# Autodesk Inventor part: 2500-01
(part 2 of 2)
sketch "Sketch56"
  geometry: L1 (2, -4.8)-(12, -4.8) reference; L2 (10.75, -6.3)-(3.25, -6.3); L3 (3.25, -6.3)-(3.25, -24.3); L4 (3.25, -24.3)-(10.75, -24.3); L5 (10.75, -24.3)-(10.75, -6.3); L6 (2, -24.3)-(12, -24.3) reference; 2 further points
  constraints: 8 end point, 2 midpoint, 2 parallel, 1 collinear, 1 horizontal, 1 perpendicular, 1 vertical alignment
  dimensions: "d457" = 18 distance of L4.end L2.start; "d458" = 7.5 distance of L2.start L2.end
extrude "Extrusion54" cut sketch "Sketch56" distance "d459" = 10; taper "d460" = 0 deg
sketch "Sketch57"
  geometry: L1 (10.75, -8.8)-(10.75, -6.3) reference; L2 (3.25, -6.3)-(3.25, -24.3) reference; L3 (10.65, -7.3)-(5.65, -7.3); L4 (5.65, -7.3)-(5.65, -23.3); L5 (5.65, -23.3)-(10.65, -23.3); L6 (10.65, -23.3)-(10.65, -7.3); 2 further points
  constraints: 8 end point, 2 midpoint, 2 parallel, 1 horizontal, 1 horizontal alignment, 1 perpendicular
  dimensions: "d461" = 0.1 distance between parallel lines of L1 L6; "d462" = 16 distance of L5.end L3.start; "d463" = 5 distance of L3.start L3.end
extrude "Extrusion55" join sketch "Sketch57" distance "d464" = 15; taper "d465" = 0 deg
chamfer "Chamfer15" distance "d466" = 3; stored, may be unused: second distance "d467" = 2, angle "d468" = 70 deg
sketch "Sketch58"
  geometry: L1 (5.65, -23.3)-(5.65, -7.3) reference; L2 (3.25, -6.3)-(3.25, -24.3) reference; L3 (5.55, -10.3)-(3.25, -10.3); L4 (3.25, -10.3)-(3.25, -20.3); L5 (3.25, -20.3)-(5.55, -20.3); L6 (5.55, -20.3)-(5.55, -10.3); L7 (5.65, -10.3)-(10.65, -10.3) reference; L8 (10.65, -20.3)-(5.65, -20.3) reference
  constraints: 8 end point, 2 collinear, 2 parallel, 1 horizontal, 1 perpendicular, 1 point on line
  dimensions: "d469" = 0.1 distance between parallel lines of L1 L6
extrude "Extrusion56" join sketch "Sketch58" distance "d470" = 9; taper "d471" = 0 deg
sketch "Sketch59"
  geometry: L1 (10.65, -10.3)-(10.65, -20.3) reference; L2 (5.65, -20.3)-(5.65, -10.3) reference; L3 (9.75, -11.8)-(6.25, -11.8); L4 (6.25, -11.8)-(6.25, -14.55); L5 (6.25, -14.55)-(9.75, -14.55); L6 (9.75, -14.55)-(9.75, -11.8); L7 (9.75, -16.05)-(6.25, -16.05); L8 (6.25, -16.05)-(6.25, -18.8); L9 (6.25, -18.8)-(9.75, -18.8); L10 (9.75, -18.8)-(9.75, -16.05); L11 (13.569, -15.3)-(3.512, -15.3); 1 further point
  constraints: 18 end point, 4 parallel, 3 perpendicular, 2 collinear, 2 horizontal, 1 midpoint, 1 point on line, 2 other
  dimensions: "d472" = 1.5 distance between parallel lines of L7 L5; "d473" = 7 distance between parallel lines of L9 L3; "d474" = 3.5 distance of L8.end L9.end; "d475" = 0.6 distance between parallel lines of L2 L8
extrude "Extrusion57" cut sketch "Sketch59" distance "d476" = 5; taper "d477" = 0 deg
workplane "Work Plane9"
sketch "Sketch60"
  geometry: L1 (-8.275, -0.875)-(-18.71, -0.875); L2 (-15, -2.25)-(-15, 0.5) reference; L3 (-9.715, -0.875)-(-9.715, -2.302); L4 (-9.715, -2.302)-(-14.223, -2.302); L5 (-9.715, -0.875)-(-15.623, -0.875); A1 r 1.864 centre (-13.799, -0.487) between (-15.623, -0.875) and (-14.223, -2.302); 1 further point
  constraints: 8 end point, 3 point on line, 2 point on circle, 1 centre point, 1 collinear, 1 horizontal, 1 midpoint, 1 parallel, 1 perpendicular
revolve "Revolution9" sketch "Sketch60" stored, may be unused: angle "d479" = 90 deg
sketch "Sketch61"
  geometry: L1 (37, -4.5)-(29.3, -4.5) reference; L2 (27.76, 0)-(38.54, 0) reference; L3 (30.9, 0)-(35.4, 0); L4 (35.4, 0)-(35.4, -5.813); L5 (35.4, -5.813)-(30.9, -5.813); L6 (30.9, -5.813)-(30.9, 0); L7 (35.4, 0)-(35.4, 5.813); L8 (35.4, 5.813)-(30.9, 5.813); L9 (30.9, 5.813)-(30.9, 0); 4 further points
  constraints: 14 end point, 4 symmetric about line, 2 midpoint, 2 parallel, 1 horizontal, 1 perpendicular, 1 point on line, 1 vertical alignment
  dimensions: "d481" = 4.5 distance between parallel lines of L4 L6
revolve "Revolution10" stored, may be unused: angle "d482" = 90 deg
extrude "Extrusion58" cut sketch "Sketch61" stored distance "d483" = 5; taper "d484" = 0 deg
sketch "Sketch62"
  geometry: L1 (0, 0)-(-7.7, 0) reference; L2 (-1.6, 0)-(-6.1, 0); L3 (-6.1, 0)-(-6.1, 3.2); L4 (-6.1, 3.2)-(-1.6, 3.2); L5 (-1.6, 3.2)-(-1.6, 0); L6 (0, 0)-(-7.7, 0) reference; 3 further points
  constraints: 8 end point, 3 midpoint, 2 coincident, 2 parallel, 1 horizontal, 1 perpendicular, 1 point on line
  dimensions: "d485" = 4.5 distance between parallel lines of L3 L5; "d486" = 3.2 distance of L4.end L2.start
extrude "Extrusion59" cut sketch "Sketch62" stored distance "d487" = 5; taper "d488" = 0 deg
sketch "Sketch63"
  geometry: C1 r 4.75 at (4.5, 5.3); C2 r 5.05 at (4.5, 5.3); A1 r 5.813 centre (4.5, 5.3) between (10.313, 5.3) and (-1.243, 6.2) reference
  constraints: 2 centre point, 2 coincident
  dimensions: "d489" = 9.5 diameter of C1; "d490" = 0.3 radial gap between concentric circles of C1 C2
extrude "Extrusion60" join sketch "Sketch63" distance "d491" = 4.3; taper "d492" = 0 deg
sketch "Sketch64"
  geometry: C1 r 4.65 at (5.813, 5.3); C2 r 3.85 at (5.813, 5.3); A1 r 5.813 centre (5.813, 5.3) between (11.626, 5.3) and (0.07, 6.2) reference; A2 r 4.75 centre (5.813, 5.3) between (10.313, 3.779) and (1.313, 3.779) reference
  constraints: 2 centre point, 2 coincident
  dimensions: "d493" = 0.1 radial gap between concentric circles of C1 A2; "d494" = 0.8 radial gap between concentric circles of C2 C1
extrude "Extrusion61" join sketch "Sketch64" stored distance "d495" = 5; taper "d496" = 0 deg
mirror "Mirror4"
sketch "Sketch65"
  geometry: L1 (84.869, 5.621)-(89.6, 10.646); L2 (89.6, 10.646)-(89.6, 16); L3 (89.6, 16)-(91.6, 16); L4 (91.6, 16)-(91.6, 10); L5 (91.6, 10)-(86.251, 4.319); L6 (76.6, -8.4)-(78.6, -8.4); L7 (78.6, -8.5)-(76.5, -8.5) reference; L8 (76.5, -8.5)-(76.5, 4.5) reference; L9 (70, -10.5)-(78.6, -10.5) reference; L10 (78.6, -8.5)-(78.6, -10.5) reference; L11 (76.6, -8.4)-(76.6, -4.412); L12 (76.6, -4.412)-(78.14, -4.412); A1 r 36.899 centre (111.735, -19.673) between (84.869, 5.621) and (76.6, -8.4); A2 r 35 centre (111.735, -19.673) between (86.251, 4.319) and (78.6, -8.4)
  constraints: 16 end point, 5 point on circle, 4 perpendicular, 2 centre point, 2 parallel, 2 tangent, 1 concentric, 1 vertical, 1 vertical alignment
  dimensions: "d500" = 0.1 distance between parallel lines of L7 L6; "d501" = 0.1 distance from line of L8 L6.start; "d503" = 26.5 distance between parallel lines of L3 L9; "d504" = 13 distance between parallel lines of L10 L4; "d505" = 2 distance between parallel lines of L4 L2; "d507" = 6 distance of L3.end L4.end; "d508" = 35 radius of A2
extrude "Extrusion62" join sketch "Sketch65" stored distance "d509" = 5; taper "d510" = 0 deg
chamfer "Chamfer16" distance "d511" = 1.5; stored, may be unused: second distance "d512" = 2, angle "d513" = 60 deg
sketch "Sketch66"
  geometry: L1 (-24.4, 14.5)-(-24.4, 15) reference; L2 (-0.2, -5.5)-(-9.7, -5.5); L3 (-9.7, -5.5)-(-9.7, -10); L4 (-9.7, -10)-(-0.2, -10); L5 (-0.2, -10)-(-0.2, -5.5); L6 (0.6, -5.4)-(-5.4, -5.4) reference; L7 (-1.2, -27.8)-(-1.2, -7.6) reference
  constraints: 8 end point, 2 parallel, 2 perpendicular
  dimensions: "d514" = 0.1 distance between parallel lines of L6 L2; "d515" = 9.5 distance of L2.start L2.end; "d516" = 1 distance between parallel lines of L5 L7; "d517" = 4.5 distance of L2.end L3.end
extrude "Extrusion63" join sketch "Sketch66" distance "d518" = 3.5; taper "d519" = 0 deg
chamfer "Chamfer17" distance "d520" = 3; stored, may be unused: second distance "d521" = 2, angle "d522" = 30 deg
workplane "Work Plane10"
sketch "Sketch67"
  geometry: L1 (9, 54.1)-(4.7, 54.1) reference; L2 (1.5, 64)-(1.5, 33) reference; L3 (13.2, 36.3)-(13.2, 54.1) reference; L4 (3.5, 54.1)-(3.5, 71.236); L5 (3.5, 54.1)-(10.5, 54.1); L6 (10.5, 54.1)-(10.5, 61.6); L7 (11.5, 62.6)-(12, 62.6); L8 (12, 62.6)-(12, 66.019); L9 (4.7, 54.1)-(7.7, 54.1) reference; A1 r 41.613 centre (29.36, 103.839) between (3.5, 71.236) and (12, 66.019); A2 r 1 centre (11.5, 61.6) between (11.5, 62.6) and (10.5, 61.6); 1 further point
  constraints: 10 end point, 4 point on circle, 3 point on line, 2 centre point, 2 parallel, 2 perpendicular, 2 tangent, 1 collinear
  dimensions: "d524" = 7 distance of L4.start L5.end; "d525" = 2 distance between parallel lines of L2 L4; "d526" = 1.5 distance between parallel lines of L6 L8; "d527" = 8.5 distance of L5.end point (10.5, 62.6); "d528" = 1 radius of A2
extrude "Extrusion64" join sketch "Sketch67" stored distance "d529" = 3.5; taper "d530" = 0 deg
chamfer "Chamfer18" distance "d531" = 1; stored, may be unused: second distance "d532" = 2, angle "d533" = 60 deg
sketch "Sketch68"
  geometry: L1 (-18.4, 15)-(-12.719, 9.651) reference; L2 (-14.4, 3.3)-(-14.4, 11.234); L3 (-10.9, -10)-(-10.9, 5.869) reference; L4 (-10.9, 7.136)-(-10.9, 5.869) reference; L5 (-10.9, 1.279)-(-10.9, 8.054); L6 (-14.4, 3.3)-(-10.9, 1.279); L7 (-10.9, -0.1)-(-12.9, -0.1) reference; A1 r 35 centre (11.273, 35.135) between (-12.719, 9.651) and (0, 2) reference
  constraints: 6 end point, 2 collinear, 2 point on line, 1 point on circle
  dimensions: "d535" = 3.5 distance between parallel lines of L3 L2; "d536" = 60 deg angle of L5 L6; "d537" = 3.4 distance from line of L7 L2.start
extrude "Extrusion65" join sketch "Sketch68" distance "d538" = 1.5; taper "d539" = 0 deg
fillet "Fillet1" dims "d541" = 1
sketch "Sketch69"
  geometry: L1 (0, 0)-(66, 0) reference; L2 (66, 0)-(66, 5.603) reference; L3 (33, 47.913)-(33, -69.621) reference; L4 (66, 10)-(63.25, 10); L5 (63.25, 10)-(58.75, 0); L6 (66, 0)-(58.75, 0); L7 (66, 0)-(66, 10); L8 (48.5, -1.774)-(48.5, 31.075); L9 (48.5, 3.5)-(52.1, 3.5); L10 (52.1, 3.5)-(52.6, 6.5); L11 (52.6, 6.5)-(48.5, 6.5); L12 (48.5, 3.5)-(44.9, 3.5); L13 (44.9, 3.5)-(44.4, 6.5); L14 (44.4, 6.5)-(48.5, 6.5); L15 (2.75, 10)-(7.25, 0); L16 (0, 0)-(7.25, 0); L17 (0, 0)-(0, 5.603); L18 (0, 0)-(0, 10); L19 (0, 10)-(2.75, 10); L20 (13.9, 3.5)-(13.4, 6.5); L21 (17.5, 3.5)-(13.9, 3.5); L22 (13.4, 6.5)-(17.5, 6.5); L23 (17.5, 3.5)-(21.1, 3.5); L24 (21.1, 3.5)-(21.6, 6.5); L25 (21.6, 6.5)-(17.5, 6.5); L26 (17.5, -1.774)-(17.5, 31.075)
  constraints: 46 end point, 13 symmetric about line, 5 point on line, 2 perpendicular, 1 collinear, 1 parallel, 1 vertical
  dimensions: "d543" = 51.5 diameter of L5.end L3; "d544" = 60.5 diameter of L4.end L3; "d545" = 10 distance from line of L4 L5.end; "d547" = 31 diameter of L8.end L3; "d552" = 7.2 diameter of L9.end L8; "d553" = 8.2 diameter of L10.end L8; "d554" = 3 distance between parallel lines of L11 L9; "d555" = 3.5 distance between parallel lines of L1 L9
extrude "Extrusion66" cut sketch "Sketch69" distance "d556" = 15; taper "d557" = 0 deg
workplane "Work Plane11"
sketch "Sketch70"
  geometry: L1 (88.892, 9.5)-(85.521, 9.5); L2 (85.521, 9.5)-(85.521, 7.5); L3 (91.129, 9.5)-(88.521, 9.5) reference; A1 r 35 centre (113.306, -13.784) between (85.521, 7.5) and (81.788, 1.436); A2 r 36.899 centre (111.735, -19.673) between (84.869, 5.621) and (78.14, -4.412) reference; 2 further points
  constraints: 4 end point, 4 point on circle, 1 centre point, 1 coincident, 1 collinear, 1 horizontal, 1 perpendicular
  dimensions: "d558" = 3 distance from line of L2 L3.end; "d559" = 35 radius of A1; "d560" = 6 horizontal distance of L3.end point (82.521, 2.868); "d561" = 2 distance from line of L2.end L1
feature "Rib1" sketch "Sketch70" dims "d562" = 1, "d563" = 1, "d564" = 0
sketch "Sketch71"
  geometry: A1 r 21.005 centre (72.171, 19.068) between (87.057, 4.249) and (90.806, 9.376); A2 r 40.752 centre (115.94, -24.5) between (87.057, 4.249) and (78.536, -8.323)
  constraints: 4 point on circle, 2 centre point, 1 tangent
feature "Rib2" sketch "Sketch71" dims "d565" = 1, "d566" = 1, "d567" = 0
mirror "Mirror5"
workplane "Work Plane12"
sketch "Sketch72"
  geometry: L1 (-4.258, 9.661)-(-5, 10.7); L2 (-5, 10.7)-(-61, 10.7); L3 (-61, 10.7)-(-61.818, 9.555); L4 (-4.42, 11.428)-(-2.75, 7.934) reference; L5 (-63.25, 7.934)-(-61.58, 11.428) reference; L6 (-52.343, 9.7)-(-60.981, 9.7) reference; L7 (-33, 34.12)-(-33, -122.82) reference
  constraints: 6 end point, 1 horizontal, 1 symmetric about line
  dimensions: "d570" = 10 deg angle of L4 L1; "d572" = 10 deg angle of L5 L3; "d573" = 1 distance between parallel lines of L6 L2; "d574" = 56 distance of L1.end L2.end
feature "Rib3" sketch "Sketch72" dims "d575" = 1, "d576" = 1, "d577" = 0
workplane "Work Plane13"
sketch "Sketch73"
  geometry: L1 (4.45, -27.15)-(4.45, -22.45) reference; L2 (4.45, -22.45)-(-9.05, -22.45); L3 (4.45, -27.15)-(-9.05, -27.15); L4 (-9.05, -27.15)-(-9.05, -22.45) reference; L5 (5.45, -22.05)-(5.45, -21.8) reference; L6 (5.45, -27.8)-(5.45, -27.55) reference; L7 (5.45, -27.55)-(4.45, -27.15) reference; L8 (4.45, -22.45)-(5.45, -22.05) reference; L9 (5.45, -21.8)-(-10.05, -21.8); L10 (5.45, -27.8)-(-10.05, -27.8); L11 (-10.05, -22.05)-(-10.05, -21.8) reference; L12 (-9.05, -22.45)-(-10.05, -22.05) reference; L13 (-10.05, -27.55)-(-9.05, -27.15) reference; L14 (-10.05, -27.8)-(-10.05, -27.55) reference
  constraints: 28 end point, 6 vertical, 18 other
extrude_surface "ExtrusionSrf1" sketch "Sketch73" dims "d579" = 50, "d580" = 0
sketch "Sketch74"
  geometry: L1 (0, 0)-(0, 16.2) reference; L2 (70.8, 0)-(0, 0) reference; L3 (10, 0)-(13.5, 0); L4 (13.5, 0)-(13.5, -10); L5 (13.5, -10)-(10, -10); L6 (10, -10)-(10, 0); L7 (17, 0)-(20.5, 0); L8 (20.5, 0)-(20.5, -10); L9 (20.5, -10)-(17, -10); L10 (17, -10)-(17, 0); L11 (64.584, -9.35)-(14.584, -9.35) reference; L12 (14.584, -9.75)-(64.584, -9.75) reference; L13 (64.584, -4.65)-(14.584, -4.65) reference; L14 (64.584, -4.25)-(14.584, -4.25) reference
  constraints: 16 end point, 4 parallel, 2 horizontal, 2 perpendicular, 2 point on line
  dimensions: "d581" = 10 distance between parallel lines of L1 L6; "d582" = 3.5 distance of L4.end L5.end; "d583" = 10 distance between parallel lines of L3 L5; "d584" = 3.5 distance between parallel lines of L8 L10 (derived); "d585" = 10 distance of L9.end L7.start (derived); "d586" = 3.5 distance between parallel lines of L10 L4 (derived)
extrude "Extrusion67" join sketch "Sketch74" stored distance "d587" = 100; taper "d588" = 0 deg
sketch "Sketch75"
  geometry: L1 (1.6, 0)-(1.6, 10) reference; L2 (0.85, 5.35)-(0.85, 0.65) reference; L3 (1.85, 5.75)-(0.85, 5.35) reference; L4 (0.85, 0.65)-(1.85, 0.25) reference; L5 (1.6, 0.35)-(0.85, 0.65); L6 (0.85, 0.65)-(0.85, 5.35); L7 (0.85, 5.35)-(1.6, 5.65); L8 (1.6, 5.65)-(1.6, 0.35)
  constraints: 8 end point, 4 point on line, 2 collinear, 1 parallel
extrude "Extrusion68" cut sketch "Sketch75" stored distance "d589" = 100; taper "d590" = 0 deg
sketch "Sketch76"
  geometry: L1 (1.6, 5.65)-(1.6, 10) reference; L2 (0.85, 0.65)-(0.85, 5.35) reference; L3 (0.85, 5.35)-(1.85, 5.75) reference; L4 (1.85, 0.25)-(0.85, 0.65) reference; L5 (1.6, 7)-(3.041, 6.007); L6 (3.041, 6.007)-(3.041, 3.339); L7 (2.341, 2.639)-(2.341, 5.639); L8 (2.341, 5.639)-(1.6, 6.15); L9 (1.6, 6.15)-(1.6, 7); L10 (3.041, 3.339)-(2.341, 2.639); L11 (3.1, 10)-(-0.1, 10) reference
  constraints: 12 end point, 2 point on line, 1 collinear, 1 parallel
  dimensions: "d591" = 0.7 distance between parallel lines of L8 L5; "d592" = 0.7 distance between parallel lines of L6 L7; "d596" = 3 distance of L7.start L7.end; "d597" = 1.75 distance of L5.start L5.end; "d599" = 0.5 distance of L1.start L8.end; "d628" = 3 distance from line of L11 L5.start; "d629" = 135 deg angle of L10 L6
extrude "Extrusion69" join sketch "Sketch76" stored distance "d604" = 100; taper "d605" = 0 deg
sketch "Sketch77"
  geometry: L1 (13.5, -10)-(13.5, 0) reference; L2 (17, 0)-(13.5, 0) reference; L3 (17, 0)-(17, -10) reference; L4 (17, -10)-(20.5, -10) reference; L5 (13.5, -10)-(17, -10)
  constraints: 2 end point, 1 collinear
extrude "Extrusion70" cut sketch "Sketch77" extent not by distance; stored distance "d606" = 100; taper "d607" = 0 deg
feature "FaceDraft2" dims angle "d609" = 2.5 deg
feature "FaceDraft3" dims angle "d610" = 2.5 deg
feature "FaceDraft4" dims angle "d611" = 2.5 deg
workplane "Work Plane14"
mirror "Mirror6"
body "Solid1"
mirror "Mirror2"
workplane "Work Plane6"
workplane "Work Plane7"
body "Srf1"
other parameters: "d90" = 7.3, "d225" = -4, "d230" = -1, "d237" = -0.5, "d242" = -0.5, "d393" = 0, "d478" = -2.5, "d523" = 0, "d540" = 15.5, "d568" = 2, "d578" = -44, "d612" = 0, "d613" = 0, "d614" = 0, "d615" = 0, "d616" = 0, "d617" = 0
